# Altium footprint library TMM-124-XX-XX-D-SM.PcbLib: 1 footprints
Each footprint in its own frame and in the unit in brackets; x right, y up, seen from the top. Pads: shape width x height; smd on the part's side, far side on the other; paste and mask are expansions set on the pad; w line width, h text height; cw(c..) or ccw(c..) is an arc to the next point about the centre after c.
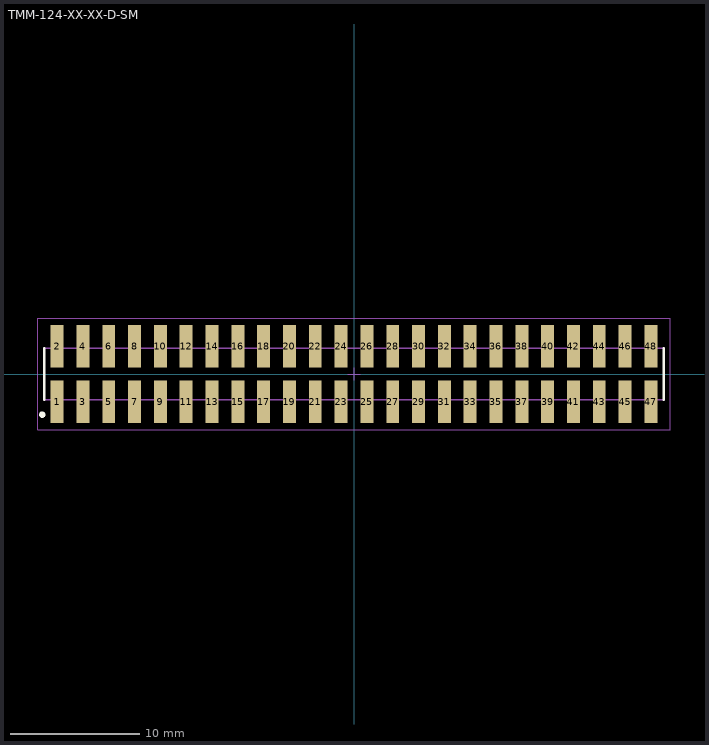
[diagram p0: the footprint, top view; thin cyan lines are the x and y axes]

## TMM-124-XX-XX-D-SM [mm] "2.00mm pitch, 48 pin, terminal strip; double row, SMT"
height 2.77
pads (48):
  rect 1x3.3 smd mask+0: 1(-23,-2.15) 2(-23,2.15) 3(-21,-2.15) 4(-21,2.15) 5(-19,-2.15) 6(-19,2.15) 7(-17,-2.15) 8(-17,2.15) 9(-15,-2.15) 10(-15,2.15) 11(-13,-2.15) 12(-13,2.15) 13(-11,-2.15) 14(-11,2.15) 15(-9,-2.15) 16(-9,2.15) 17(-7,-2.15) 18(-7,2.15) 19(-5,-2.15) 20(-5,2.15) 21(-3,-2.15) 22(-3,2.15) 23(-1,-2.15) 24(-1,2.15) 25(1,-2.15) 26(1,2.15) 27(3,-2.15) 28(3,2.15) 29(5,-2.15) 30(5,2.15) 31(7,-2.15) 32(7,2.15) 33(9,-2.15) 34(9,2.15) 35(11,-2.15) 36(11,2.15) 37(13,-2.15) 38(13,2.15) 39(15,-2.15) 40(15,2.15) 41(17,-2.15) 42(17,2.15) 43(19,-2.15) 44(19,2.15) 45(21,-2.15) 46(21,2.15) 47(23,-2.15) 48(23,2.15)
Top Overlay:
  circle w0.25: c-24.15,-3.15 r0.125
  lines w0.2: -24,-2 -24,2 ; 24,-2 24,2
Mechanical 12:
  lines w0.001: -24,-2 24,-2 24,2 -24,2 -24,-2
Mechanical 13:
  lines w0.1: -24,-2 24,-2 24,2 -24,2 -24,-2
  text ".Designator" at 0,-0.127 h1.52
Mechanical 15:
  lines w0.05: -0.5,0 0.5,0 ; 0,-0.5 0,0.5 ; -24.5,-4.3 24.5,-4.3 24.5,4.3 -24.5,4.3 -24.5,-4.3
